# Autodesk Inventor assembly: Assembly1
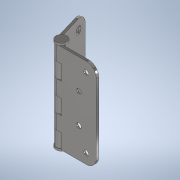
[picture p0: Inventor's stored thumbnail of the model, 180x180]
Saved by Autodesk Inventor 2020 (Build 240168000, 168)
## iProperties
Created: 2023-04
Part Number: Assembly1
Document SubType Name: Assembly
Designer: gzb
Author: gzb
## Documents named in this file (3)
- C:\Users\gzb\Desktop\Youtube\19- HINGE\Assembly1.iam
- C:\Users\gzb\Desktop\Youtube\19- HINGE\PART-1.ipt
- C:\Users\gzb\Desktop\Youtube\19- HINGE\PIN.ipt
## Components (3 placed, 2 different names)
1. PART-1:1 — Mate:1, Flush:1, Mate:2, Mate:3, Mate:4
2. PART-1:2 — Mate:3, Mate:4, Mate:5, Mate:6
3. PIN:1 — Mate:5, Mate:6
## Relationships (7: Mate 6, Flush 1)
- Mate:1: PART-1:1
- Flush:1: PART-1:1
- Mate:2: PART-1:1
- Mate:3: PART-1:1 ↔ PART-1:2
- Mate:4: PART-1:1 ↔ PART-1:2
- Mate:5: PART-1:2 ↔ PIN:1
- Mate:6: PART-1:2 ↔ PIN:1
